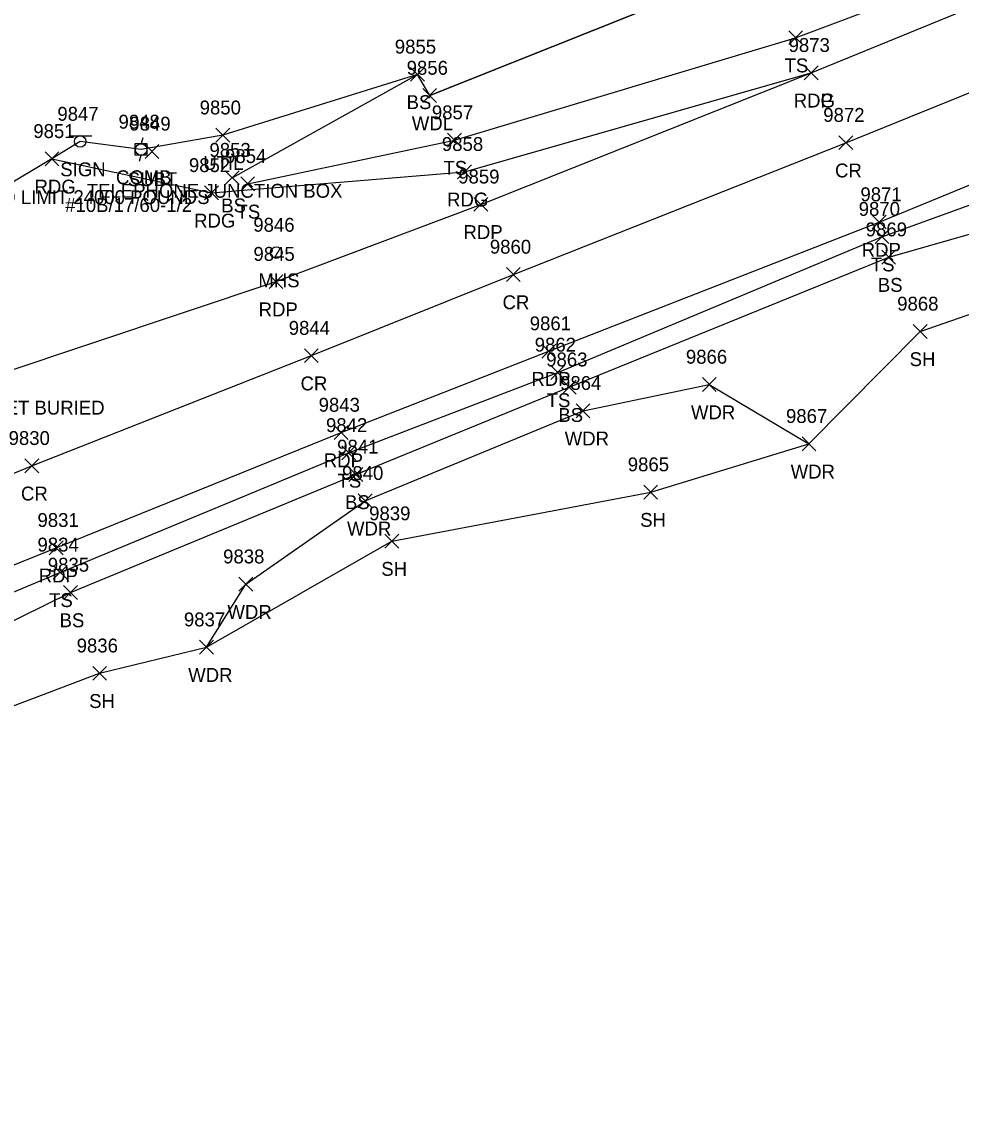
# Model space of a CAD drawing. Extents: x 1651685 to 1653558, y 889533 to 891085.
# Drawn here: x 1652071.5 to 1652207, y 889700.1 to 889855.7 of the extents above; entities that cross this region are included whole.
import ezdxf

# ---------------------------------------------------------------- set-up
doc = ezdxf.new("R2010")
doc.units = 0
for name, color, linetype in [('D_C', 7, 'Continuous'), ('L_A', 7, 'Continuous'), ('L_I', 7, 'Continuous'), ('L_TIC', 7, 'Continuous'), ('LAWA', 7, 'Continuous'), ('LELB', 7, 'Continuous'), ('LSOGP', 7, 'Continuous'), ('P_A', 7, 'Continuous'), ('P_I', 7, 'Continuous'), ('P_TIC', 7, 'Continuous'), ('PET', 7, 'Continuous'), ('PEU', 7, 'Continuous'), ('PRC', 7, 'Continuous'), ('S_A', 7, 'Continuous'), ('S_C', 7, 'Continuous'), ('S_I', 7, 'Continuous'), ('SSGN', 7, 'Continuous'), ('U_A', 7, 'Continuous'), ('U_C', 7, 'Continuous'), ('U_I', 7, 'Continuous'), ('U_TIC', 7, 'Continuous'), ('UDEFAULT', 7, 'Continuous'), ('UP', 7, 'Continuous'), ('USMH', 7, 'Continuous')]:
    doc.layers.add(name, color=color, linetype=linetype)

msp = doc.modelspace()

# ---------------------------------------------------------------- linework, layer by layer
at = {"layer": 'L_TIC'}
for points in [[(1652182.13, 889852.37), (1652184.13, 889854.37)], [(1652184.13, 889852.37), (1652182.13, 889854.37)], [(1652127.61, 889847.08), (1652129.61, 889849.08)], [(1652129.61, 889847.08), (1652127.61, 889849.08)], [(1652129.38, 889844.03), (1652131.38, 889846.03)], [(1652131.38, 889844.03), (1652129.38, 889846.03)], [(1652132.95, 889837.61), (1652134.95, 889839.61)], [(1652134.95, 889837.61), (1652132.95, 889839.61)], [(1652100.89, 889832.2), (1652102.89, 889834.2)], [(1652102.89, 889832.2), (1652100.89, 889834.2)], [(1652103.14, 889831.31), (1652105.14, 889833.31)], [(1652105.14, 889831.31), (1652103.14, 889833.31)], [(1652194.57, 889823.7), (1652196.57, 889825.7)], [(1652196.57, 889823.7), (1652194.57, 889825.7)], [(1652195.54, 889820.75), (1652197.54, 889822.75)], [(1652197.54, 889820.75), (1652195.54, 889822.75)], [(1652200.08, 889810.05), (1652202.08, 889812.05)], [(1652202.08, 889810.05), (1652200.08, 889812.05)], [(1652147.83, 889804.14), (1652149.83, 889806.14)], [(1652149.83, 889804.14), (1652147.83, 889806.14)], [(1652149.48, 889802.01), (1652151.48, 889804.01)], [(1652151.48, 889802.01), (1652149.48, 889804.01)], [(1652169.68, 889802.4), (1652171.68, 889804.4)], [(1652171.68, 889802.4), (1652169.68, 889804.4)], [(1652151.48, 889798.62), (1652153.48, 889800.62)], [(1652153.48, 889798.62), (1652151.48, 889800.62)], [(1652184.05, 889793.86), (1652186.05, 889795.86)], [(1652186.05, 889793.86), (1652184.05, 889795.86)], [(1652117.69, 889792.55), (1652119.69, 889794.55)], [(1652119.69, 889792.55), (1652117.69, 889794.55)], [(1652118.73, 889789.45), (1652120.73, 889791.45)], [(1652120.73, 889789.45), (1652118.73, 889791.45)], [(1652161.24, 889786.9), (1652163.24, 889788.9)], [(1652163.24, 889786.9), (1652161.24, 889788.9)], [(1652120.09, 889785.65), (1652122.09, 889787.65)], [(1652122.09, 889785.65), (1652120.09, 889787.65)], [(1652123.91, 889779.84), (1652125.91, 889781.84)], [(1652125.91, 889779.84), (1652123.91, 889781.84)], [(1652076.1, 889775.34), (1652078.1, 889777.34)], [(1652078.1, 889775.34), (1652076.1, 889777.34)], [(1652102.86, 889773.63), (1652104.86, 889775.63)], [(1652104.86, 889773.63), (1652102.86, 889775.63)], [(1652077.59, 889772.44), (1652079.59, 889774.44)], [(1652079.59, 889772.44), (1652077.59, 889774.44)], [(1652097.21, 889764.56), (1652099.21, 889766.56)], [(1652099.21, 889764.56), (1652097.21, 889766.56)], [(1652081.8, 889760.8), (1652083.8, 889762.8)], [(1652083.8, 889760.8), (1652081.8, 889762.8)]]:
    msp.add_lwpolyline(points, dxfattribs=at)
at = {"layer": 'LAWA'}
for points in [[(1652130.38, 889845.03), (1652177.7, 889863.93), (1652189.89, 889872.39)], [(1652098.21, 889765.56), (1652103.86, 889774.63), (1652121.09, 889786.65), (1652152.48, 889799.62), (1652170.68, 889803.4), (1652185.05, 889794.86)]]:
    msp.add_lwpolyline(points, dxfattribs=at)
at = {"layer": 'LELB'}
for points in [[(1652059.96, 889769.15), (1652077.1, 889776.34), (1652118.69, 889793.55), (1652148.83, 889805.14), (1652195.57, 889824.7), (1652235.22, 889839.02), (1652273.17, 889851.71), (1652312.19, 889868.5), (1652346.46, 889887.35), (1652384.44, 889904.89), (1652418.63, 889927.64), (1652449.26, 889948.79), (1652484.18, 889973.18), (1652505.9, 889994.66), (1652536.9, 890025.51), (1652566.28, 890055.69), (1652594.63, 890083.58), (1652622.18, 890122.04), (1652650.06, 890154.47), (1652669.87, 890181.83), (1652676.09, 890189.41), (1652687.77, 890202.23), (1652700.09, 890224.17)], [(1652104.14, 889832.31), (1652133.95, 889838.61), (1652183.13, 889853.37), (1652222.17, 889868.05), (1652260.83, 889884.17), (1652274.76, 889892.87), (1652271.19, 889906.55)], [(1652064.04, 889766.3), (1652078.59, 889773.44), (1652119.73, 889790.45), (1652150.48, 889803.01), (1652196.54, 889821.75), (1652237.97, 889833.58), (1652274.81, 889846.26), (1652318.57, 889855.03)], [(1652101.89, 889833.2), (1652128.61, 889848.08)]]:
    msp.add_lwpolyline(points, dxfattribs=at)
at = {"layer": 'LSOGP'}
for points in [[(1652344.51, 889962.98), (1652311.88, 889950.06), (1652319.83, 889936.28), (1652297.31, 889917.06), (1652293.22, 889915.65), (1652288.54, 889913.18), (1652275.12, 889907.88), (1652271.2, 889906.55), (1652269.1, 889906.41), (1652254.49, 889898.49), (1652214.38, 889884.21), (1652189.89, 889872.39), (1652177.7, 889863.92), (1652130.38, 889845.03), (1652128.61, 889848.08), (1652100.57, 889839.31), (1652088.78, 889837.26), (1652079.97, 889838.39), (1652075.93, 889835.91), (1652046.4, 889818.27), (1652039.29, 889812.4), (1652028.35, 889807.39), (1651985.79, 889786.86)], [(1651980.89, 889713.26), (1652008.19, 889730.53), (1652031.23, 889739.86), (1652043.32, 889745.77), (1652059.06, 889752.82), (1652082.8, 889761.8), (1652098.21, 889765.57), (1652124.91, 889780.84), (1652162.24, 889787.9), (1652185.04, 889794.86), (1652201.07, 889811.05), (1652242.25, 889825.35), (1652276.97, 889838.55), (1652318.58, 889855.03), (1652374.55, 889845.16)]]:
    msp.add_lwpolyline(points, dxfattribs=at)
at = {"layer": 'P_TIC'}
for points in [[(1652184.37, 889847.31), (1652186.37, 889849.31)], [(1652186.37, 889847.31), (1652184.37, 889849.31)], [(1652184.37, 889847.31), (1652186.37, 889849.31)], [(1652186.37, 889847.31), (1652184.37, 889849.31)], [(1652189.37, 889837.24), (1652191.37, 889839.24)], [(1652191.37, 889837.24), (1652189.37, 889839.24)], [(1652074.93, 889834.91), (1652076.93, 889836.91)], [(1652076.93, 889834.91), (1652074.93, 889836.91)], [(1652134.4, 889833.05), (1652136.4, 889835.05)], [(1652136.4, 889833.05), (1652134.4, 889835.05)], [(1652097.93, 889830.01), (1652099.93, 889832.01)], [(1652099.93, 889830.01), (1652097.93, 889832.01)], [(1652136.76, 889828.36), (1652138.76, 889830.36)], [(1652138.76, 889828.36), (1652136.76, 889830.36)], [(1652194.16, 889825.81), (1652196.16, 889827.81)], [(1652196.16, 889825.81), (1652194.16, 889827.81)], [(1652107.23, 889817.22), (1652109.23, 889819.22)], [(1652109.23, 889817.22), (1652107.23, 889819.22)], [(1652141.44, 889818.25), (1652143.44, 889820.25)], [(1652143.44, 889818.25), (1652141.44, 889820.25)], [(1652112.32, 889806.56), (1652114.32, 889808.56)], [(1652114.32, 889806.56), (1652112.32, 889808.56)], [(1652146.54, 889807.21), (1652148.54, 889809.21)], [(1652148.54, 889807.21), (1652146.54, 889809.21)], [(1652116.63, 889795.48), (1652118.63, 889797.48)], [(1652118.63, 889795.48), (1652116.63, 889797.48)], [(1652072.02, 889790.69), (1652074.02, 889792.69)], [(1652074.02, 889790.69), (1652072.02, 889792.69)], [(1652075.54, 889778.88), (1652077.54, 889780.88)], [(1652077.54, 889778.88), (1652075.54, 889780.88)]]:
    msp.add_lwpolyline(points, dxfattribs=at)
at = {"layer": 'PET'}
for points in [[(1651993.09, 889770.39), (1652035.55, 889788.28), (1652064.19, 889800.06), (1652068.27, 889804.89), (1652108.23, 889818.22), (1652137.76, 889829.36), (1652185.37, 889848.31), (1652223.8, 889864.06), (1652262.57, 889880.14), (1652279.91, 889887.76), (1652294.79, 889894.11), (1652333.65, 889912.67), (1652369.12, 889931.53)], [(1651722.05, 889556.64), (1651743.79, 889579.05), (1651773.7, 889607.56), (1651801.99, 889632.45), (1651834.2, 889657.45), (1651868.37, 889681.24), (1651890.21, 889694.54), (1651910.42, 889705.67), (1651932.43, 889717.43), (1651971.73, 889735.64), (1652001.72, 889748.76), (1652035.56, 889763.08), (1652038.22, 889762.81), (1652052.59, 889768.76), (1652053.52, 889770.62), (1652076.54, 889779.88), (1652117.63, 889796.48), (1652147.54, 889808.21), (1652195.16, 889826.81), (1652233.48, 889842.54), (1652271.73, 889857.62), (1652310.07, 889873.86), (1652345.02, 889890.88)]]:
    msp.add_lwpolyline(points, dxfattribs=at)
at = {"layer": 'PEU'}
msp.add_lwpolyline([(1652075.93, 889835.91), (1652098.93, 889831.01), (1652135.4, 889834.05), (1652185.37, 889848.31)], dxfattribs=at)
at = {"layer": 'PRC'}
msp.add_lwpolyline([(1651712.82, 889564.71), (1651734.46, 889586.87), (1651766.27, 889617.28), (1651793.27, 889641.25), (1651826.92, 889667.91), (1651862.27, 889692.04), (1651896.77, 889712.72), (1651926.87, 889728.69), (1651966.67, 889747.09), (1651996.7, 889760.13), (1652040.05, 889778.15), (1652073.02, 889791.69), (1652113.32, 889807.56), (1652142.44, 889819.25), (1652190.37, 889838.24), (1652228.92, 889853.82), (1652266.92, 889869.48), (1652304.43, 889885.84), (1652339.13, 889902.36), (1652374.76, 889921.45)], dxfattribs=at)
at = {"layer": 'SSGN'}
for p, q in [((1652078.35, 889839.25), (1652081.68, 889839.25)), ((1652079.99, 889838.42), (1652079.99, 889838.42))]:
    msp.add_line(p, q, dxfattribs=at)
msp.add_circle((1652079.99, 889838.42), 0.833, dxfattribs=at)
at = {"layer": 'U_TIC'}
for points in [[(1652089.35, 889835.98), (1652091.35, 889837.98)], [(1652091.35, 889835.98), (1652089.35, 889837.98)]]:
    msp.add_lwpolyline(points, dxfattribs=at)
at = {"layer": 'UDEFAULT'}
for points in [[(1652099.57, 889838.31), (1652101.57, 889840.31)], [(1652101.57, 889838.31), (1652099.57, 889840.31)]]:
    msp.add_lwpolyline(points, dxfattribs=at)
at = {"layer": 'UP'}
for p, q in [((1652087.94, 889836.43), (1652087.94, 889838.1)), ((1652087.94, 889838.1), (1652089.61, 889838.1)), ((1652089.03, 889838.93), (1652088.78, 889838.1)), ((1652089.61, 889838.1), (1652089.61, 889836.43)), ((1652089.61, 889836.43), (1652087.94, 889836.43)), ((1652088.53, 889835.6), (1652088.78, 889836.43)), ((1652088.78, 889837.26), (1652088.78, 889837.26))]:
    msp.add_line(p, q, dxfattribs=at)
msp.add_circle((1652088.78, 889837.26), 0.833, dxfattribs=at)
at = {"layer": 'USMH'}
for p, q in [((1652108.26, 889822.41), (1652108.26, 889822.41)), ((1652109.1, 889822.41), (1652109.1, 889822.41))]:
    msp.add_line(p, q, dxfattribs=at)
msp.add_circle((1652108.26, 889822.41), 0.833, dxfattribs=at)

# ---------------------------------------------------------------- texts
at = {"layer": 'D_C'}
msp.add_text('15 CGMP PLUGGED OUTLET BURIED', height=2, dxfattribs=at).set_placement((1652035.81, 889799.07))
at = {"layer": 'L_A'}
for s, p in [('TS', (1652181.54, 889848.37)), ('BS', (1652127.05, 889843.08)), ('WDL', (1652127.8, 889840.03)), ('TS', (1652132.36, 889833.61)), ('BS', (1652100.33, 889828.2)), ('TS', (1652102.54, 889827.31)), ('TS', (1652193.97, 889819.7)), ('BS', (1652194.98, 889816.75)), ('SH', (1652199.56, 889806.05)), ('TS', (1652147.24, 889800.14)), ('WDR', (1652168.04, 889798.4)), ('BS', (1652148.92, 889798.01)), ('WDR', (1652149.84, 889794.62)), ('WDR', (1652182.41, 889789.86)), ('TS', (1652117.1, 889788.55)), ('BS', (1652118.17, 889785.45)), ('SH', (1652160.72, 889782.9)), ('WDR', (1652118.46, 889781.65)), ('SH', (1652123.4, 889775.84)), ('TS', (1652075.51, 889771.34)), ('WDR', (1652101.22, 889769.63)), ('BS', (1652077.03, 889768.44)), ('WDR', (1652095.57, 889760.56)), ('SH', (1652081.29, 889756.8))]:
    msp.add_text(s, height=2, dxfattribs=at).set_placement(p)
at = {"layer": 'L_I'}
for s, p in [('9855', (1652125.35, 889851.08)), ('9856', (1652127.06, 889848.03)), ('9857', (1652130.69, 889841.61)), ('9853', (1652098.63, 889836.2)), ('9854', (1652100.88, 889835.31)), ('9870', (1652192.22, 889827.7)), ('9869', (1652193.23, 889824.75)), ('9868', (1652197.77, 889814.05)), ('9862', (1652145.52, 889808.14)), ('9863', (1652147.17, 889806.01)), ('9866', (1652167.31, 889806.4)), ('9864', (1652149.17, 889802.62)), ('9867', (1652181.74, 889797.86)), ('9842', (1652115.43, 889796.55)), ('9841', (1652117.04, 889793.45)), ('9865', (1652158.93, 889790.9)), ('9840', (1652117.75, 889789.65)), ('9839', (1652121.65, 889783.84)), ('9834', (1652073.84, 889779.34)), ('9835', (1652075.33, 889776.44)), ('9838', (1652100.6, 889777.63)), ('9837', (1652094.95, 889768.56)), ('9836', (1652079.49, 889764.8))]:
    msp.add_text(s, height=2, dxfattribs=at).set_placement(p)
at = {"layer": 'P_A'}
for s, p in [('RDG', (1652182.85, 889843.31)), ('RDP', (1652182.85, 889843.31)), ('CR', (1652188.81, 889833.24)), ('RDG', (1652073.42, 889830.91)), ('RDG', (1652132.88, 889829.05)), ('RDG', (1652096.42, 889826.01)), ('RDP', (1652135.25, 889824.36)), ('RDP', (1652192.65, 889821.81)), ('CR', (1652140.88, 889814.25)), ('RDP', (1652105.72, 889813.22)), ('RDP', (1652145.03, 889803.21)), ('CR', (1652111.76, 889802.56)), ('RDP', (1652115.12, 889791.48)), ('CR', (1652071.46, 889786.69)), ('RDP', (1652074.02, 889774.88))]:
    msp.add_text(s, height=2, dxfattribs=at).set_placement(p)
at = {"layer": 'P_I'}
for s, p in [('9873', (1652182.11, 889851.31)), ('9873', (1652182.11, 889851.31)), ('9872', (1652187.11, 889841.24)), ('9851', (1652073.24, 889838.91)), ('9858', (1652132.14, 889837.05)), ('9852', (1652095.67, 889834.01)), ('9859', (1652134.49, 889832.36)), ('9871', (1652192.47, 889829.81)), ('9860', (1652139.05, 889822.25)), ('9845', (1652104.97, 889821.22)), ('9861', (1652144.8, 889811.21)), ('9844', (1652110.06, 889810.56)), ('9843', (1652114.37, 889799.48)), ('9830', (1652069.68, 889794.69)), ('9831', (1652073.84, 889782.88))]:
    msp.add_text(s, height=2, dxfattribs=at).set_placement(p)
at = {"layer": 'S_A'}
msp.add_text('SIGN', height=2, dxfattribs=at).set_placement((1652077.13, 889833.4))
at = {"layer": 'S_C'}
msp.add_text('LEGAL LOAD LIMIT 24000 POUNDS', height=2, dxfattribs=at).set_placement((1652054.05, 889829.4))
at = {"layer": 'S_I'}
msp.add_text('9847', height=2, dxfattribs=at).set_placement((1652076.71, 889841.4))
at = {"layer": 'U_A'}
for s, p in [('UTIL', (1652097.74, 889834.31)), ('COMB', (1652085.16, 889832.26)), ('SUBT', (1652086.85, 889831.98)), ('MHS', (1652105.68, 889817.41))]:
    msp.add_text(s, height=2, dxfattribs=at).set_placement(p)
at = {"layer": 'U_C'}
for s, p in [('TELEPHONE JUNCTION BOX', (1652080.95, 889830.31)), ('#10B/17/60-1/2', (1652077.83, 889828.26))]:
    msp.add_text(s, height=2, dxfattribs=at).set_placement(p)
at = {"layer": 'U_I'}
for s, p in [('9850', (1652097.22, 889842.31)), ('9848', (1652085.52, 889840.26)), ('9849', (1652087.09, 889839.98)), ('9846', (1652104.95, 889825.41))]:
    msp.add_text(s, height=2, dxfattribs=at).set_placement(p)

doc.saveas('drawing.dxf')
